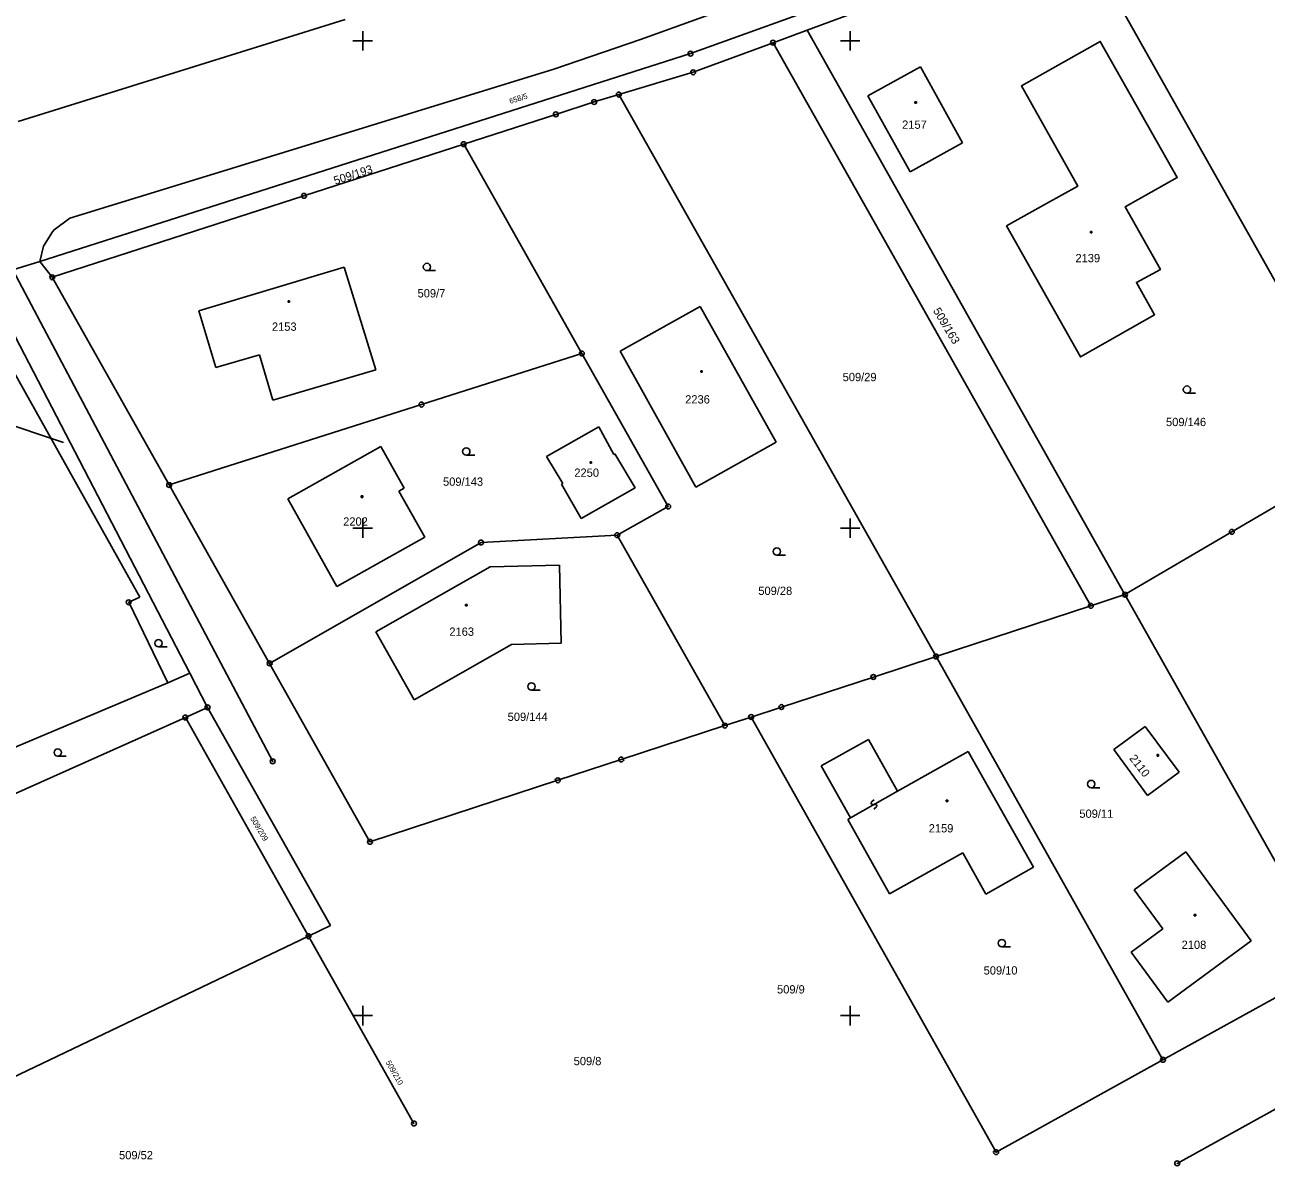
# Model space of a CAD drawing. Extents: x -493648 to -493033, y -1127718 to -1127026.
# Drawn here: x -493284.7 to -493157.3, y -1127716.4 to -1127598.4 of the extents above; entities that cross this region are included whole.
import ezdxf

# ---------------------------------------------------------------- set-up
doc = ezdxf.new("R2010")
doc.units = 0
doc.layers.add('katastrální mapa', color=7, linetype='Continuous')
doc.layers.add('síť', color=7, linetype='Continuous')

msp = doc.modelspace()

# ---------------------------------------------------------------- linework, layer by layer
at = {"layer": 'katastrální mapa'}
for p, q in [((-493178.63, -1127585.2), (-493150.81, -1127634.64)), ((-493191.17, -1127592.22), (-493216.38, -1127601.32)), ((-493204.41, -1127598.9), (-493192.39, -1127594.46)), ((-493285.34, -1127608.28), (-493251.78, -1127597.83)), ((-493207.91, -1127600.2), (-493204.41, -1127598.9)), ((-493171.81, -1127656.82), (-493204.41, -1127598.9)), ((-493216.1, -1127603.23), (-493207.91, -1127600.2)), ((-493175.31, -1127657.97), (-493207.91, -1127600.2)), ((-493283.12, -1127622.63), (-493216.38, -1127601.32)), ((-493192.8, -1127602.67), (-493198.17, -1127605.66)), ((-493188.47, -1127610.48), (-493192.8, -1127602.67)), ((-493223.72, -1127605.52), (-493216.1, -1127603.23)), ((-493226.26, -1127606.28), (-493223.72, -1127605.52)), ((-493223.72, -1127605.52), (-493191.19, -1127663.16)), ((-493198.17, -1127605.66), (-493193.84, -1127613.46)), ((-493230.19, -1127607.55), (-493226.26, -1127606.28)), ((-493193.36, -1127606.26), (-493193.21, -1127606.26)), ((-493193.36, -1127606.41), (-493193.36, -1127606.26)), ((-493193.21, -1127606.41), (-493193.36, -1127606.41)), ((-493193.21, -1127606.26), (-493193.21, -1127606.41)), ((-493239.64, -1127610.61), (-493230.19, -1127607.55)), ((-493256.02, -1127615.91), (-493239.64, -1127610.61)), ((-493227.52, -1127632.08), (-493239.64, -1127610.61)), ((-493193.84, -1127613.46), (-493188.47, -1127610.48)), ((-493281.84, -1127624.26), (-493256.02, -1127615.91)), ((-493175.36, -1127619.56), (-493175.21, -1127619.56)), ((-493175.36, -1127619.71), (-493175.36, -1127619.56)), ((-493175.21, -1127619.56), (-493175.21, -1127619.71)), ((-493175.21, -1127619.71), (-493175.36, -1127619.71)), ((-493285.88, -1127623.51), (-493283.12, -1127622.63)), ((-493285.88, -1127623.51), (-493259.23, -1127673.92)), ((-493281.84, -1127624.26), (-493283.12, -1127622.63)), ((-493251.9, -1127623.22), (-493266.82, -1127627.69)), ((-493248.64, -1127633.74), (-493251.9, -1127623.22)), ((-493288.74, -1127624.42), (-493267.72, -1127664.89)), ((-493281.84, -1127624.26), (-493269.85, -1127645.57)), ((-493243.41, -1127623.58), (-493242.53, -1127623.58)), ((-493290.17, -1127626.16), (-493272.87, -1127657.09)), ((-493257.64, -1127626.67), (-493257.49, -1127626.67)), ((-493257.64, -1127626.82), (-493257.64, -1127626.67)), ((-493257.49, -1127626.82), (-493257.64, -1127626.82)), ((-493257.49, -1127626.67), (-493257.49, -1127626.82)), ((-493215.38, -1127627.25), (-493223.6, -1127631.85)), ((-493207.59, -1127641.19), (-493215.38, -1127627.25)), ((-493266.82, -1127627.69), (-493265.05, -1127633.53)), ((-493265.05, -1127633.53), (-493260.6, -1127632.21)), ((-493260.6, -1127632.21), (-493259.2, -1127636.87)), ((-493243.97, -1127637.32), (-493227.52, -1127632.08)), ((-493218.66, -1127647.77), (-493227.52, -1127632.08)), ((-493223.6, -1127631.85), (-493215.82, -1127645.79)), ((-493259.2, -1127636.87), (-493248.64, -1127633.74)), ((-493215.33, -1127633.85), (-493215.18, -1127633.85)), ((-493215.33, -1127634), (-493215.33, -1127633.85)), ((-493215.18, -1127634), (-493215.33, -1127634)), ((-493215.18, -1127633.85), (-493215.18, -1127634)), ((-493165.45, -1127636.16), (-493164.57, -1127636.16)), ((-493269.85, -1127645.57), (-493243.97, -1127637.32)), ((-493280.68, -1127641.22), (-493287.85, -1127638.82)), ((-493225.79, -1127639.6), (-493231.14, -1127642.64)), ((-493225.79, -1127639.6), (-493224.24, -1127642.43)), ((-493215.82, -1127645.79), (-493207.59, -1127641.19)), ((-493257.69, -1127646.98), (-493248.13, -1127641.62)), ((-493248.13, -1127641.62), (-493245.73, -1127645.89)), ((-493239.37, -1127642.51), (-493238.49, -1127642.51)), ((-493224.24, -1127642.43), (-493224.13, -1127642.37)), ((-493222.06, -1127645.87), (-493224.13, -1127642.37)), ((-493160.85, -1127650.38), (-493146.64, -1127642.04)), ((-493229.48, -1127645.43), (-493231.14, -1127642.64)), ((-493226.67, -1127643.18), (-493226.52, -1127643.18)), ((-493226.67, -1127643.33), (-493226.67, -1127643.18)), ((-493226.52, -1127643.33), (-493226.67, -1127643.33)), ((-493226.52, -1127643.18), (-493226.52, -1127643.33)), ((-493269.85, -1127645.57), (-493259.55, -1127663.87)), ((-493245.73, -1127645.89), (-493246.3, -1127646.21)), ((-493246.3, -1127646.21), (-493243.64, -1127650.93)), ((-493229.61, -1127645.5), (-493229.48, -1127645.43)), ((-493229.61, -1127645.5), (-493227.58, -1127649.01)), ((-493227.58, -1127649.01), (-493222.06, -1127645.87)), ((-493252.65, -1127655.98), (-493257.69, -1127646.98)), ((-493250.14, -1127646.69), (-493249.99, -1127646.69)), ((-493250.14, -1127646.84), (-493250.14, -1127646.69)), ((-493249.99, -1127646.84), (-493250.14, -1127646.84)), ((-493249.99, -1127646.69), (-493249.99, -1127646.84)), ((-493223.89, -1127650.72), (-493218.66, -1127647.77)), ((-493259.55, -1127663.87), (-493237.86, -1127651.47)), ((-493243.64, -1127650.93), (-493252.65, -1127655.98)), ((-493223.89, -1127650.72), (-493237.86, -1127651.47)), ((-493223.89, -1127650.72), (-493212.86, -1127670.25)), ((-493160.85, -1127650.38), (-493171.81, -1127656.82)), ((-493207.52, -1127652.77), (-493206.64, -1127652.77)), ((-493248.66, -1127660.64), (-493236.94, -1127653.95)), ((-493236.94, -1127653.95), (-493229.8, -1127653.8)), ((-493229.8, -1127653.8), (-493229.63, -1127661.81)), ((-493272.87, -1127657.09), (-493274, -1127657.6)), ((-493274, -1127657.6), (-493269.99, -1127665.85)), ((-493239.44, -1127657.83), (-493239.29, -1127657.83)), ((-493239.44, -1127657.98), (-493239.44, -1127657.83)), ((-493239.29, -1127657.83), (-493239.29, -1127657.98)), ((-493175.31, -1127657.97), (-493171.81, -1127656.82)), ((-493171.81, -1127656.82), (-493150.41, -1127694.85)), ((-493239.29, -1127657.98), (-493239.44, -1127657.98)), ((-493191.19, -1127663.16), (-493175.31, -1127657.97)), ((-493244.72, -1127667.6), (-493248.66, -1127660.64)), ((-493270.94, -1127662.18), (-493270.06, -1127662.18)), ((-493234.74, -1127661.92), (-493244.72, -1127667.6)), ((-493229.63, -1127661.81), (-493234.74, -1127661.92)), ((-493259.55, -1127663.87), (-493249.25, -1127682.17)), ((-493197.62, -1127665.27), (-493191.19, -1127663.16)), ((-493191.19, -1127663.16), (-493167.91, -1127704.53)), ((-493269.99, -1127665.85), (-493267.72, -1127664.89)), ((-493267.72, -1127664.89), (-493265.91, -1127668.38)), ((-493207.05, -1127668.35), (-493197.62, -1127665.27)), ((-493269.99, -1127665.85), (-493287.47, -1127673.23)), ((-493232.69, -1127666.62), (-493231.81, -1127666.62)), ((-493268.19, -1127669.42), (-493265.91, -1127668.38)), ((-493265.91, -1127668.38), (-493253.3, -1127690.77)), ((-493210.16, -1127669.37), (-493207.05, -1127668.35)), ((-493322.12, -1127693.53), (-493268.19, -1127669.42)), ((-493255.56, -1127691.86), (-493268.19, -1127669.42)), ((-493212.86, -1127670.25), (-493223.48, -1127673.73)), ((-493210.16, -1127669.37), (-493212.86, -1127670.25)), ((-493210.16, -1127669.37), (-493185.03, -1127714.01)), ((-493172.97, -1127672.71), (-493169.75, -1127670.33)), ((-493169.75, -1127670.33), (-493166.25, -1127675.04)), ((-493202.96, -1127674.39), (-493198.11, -1127671.69)), ((-493198.11, -1127671.69), (-493195.13, -1127676.98)), ((-493195.13, -1127676.98), (-493187.9, -1127672.91)), ((-493187.9, -1127672.91), (-493181.21, -1127684.78)), ((-493169.49, -1127677.43), (-493172.97, -1127672.71)), ((-493281.28, -1127673.39), (-493280.4, -1127673.39)), ((-493229.99, -1127675.86), (-493223.48, -1127673.73)), ((-493199.97, -1127679.7), (-493202.96, -1127674.39)), ((-493168.51, -1127673.23), (-493168.36, -1127673.23)), ((-493168.51, -1127673.38), (-493168.51, -1127673.23)), ((-493168.36, -1127673.38), (-493168.51, -1127673.38)), ((-493168.36, -1127673.23), (-493168.36, -1127673.38)), ((-493166.25, -1127675.04), (-493169.49, -1127677.43)), ((-493249.25, -1127682.17), (-493229.99, -1127675.86)), ((-493199.97, -1127679.7), (-493195.13, -1127676.98)), ((-493175.27, -1127676.62), (-493174.39, -1127676.62)), ((-493197.81, -1127678.08), (-493197.85, -1127678.22)), ((-493197.85, -1127678.22), (-493197.8, -1127678.31)), ((-493197.53, -1127677.87), (-493197.81, -1127678.08)), ((-493190.14, -1127677.89), (-493189.99, -1127677.89)), ((-493190.14, -1127678.04), (-493190.14, -1127677.89)), ((-493189.99, -1127678.04), (-493190.14, -1127678.04)), ((-493189.99, -1127677.89), (-493189.99, -1127678.04)), ((-493197.8, -1127678.31), (-493197.66, -1127678.35)), ((-493197.66, -1127678.35), (-493197.44, -1127678.33)), ((-493197.29, -1127678.6), (-493197.57, -1127678.81)), ((-493197.44, -1127678.33), (-493197.3, -1127678.37)), ((-493197.3, -1127678.37), (-493197.25, -1127678.46)), ((-493197.25, -1127678.46), (-493197.29, -1127678.6)), ((-493200.25, -1127679.87), (-493199.97, -1127679.7)), ((-493200.25, -1127679.87), (-493195.95, -1127687.52)), ((-493195.95, -1127687.52), (-493188.44, -1127683.3)), ((-493188.44, -1127683.3), (-493186.07, -1127687.53)), ((-493165.58, -1127683.21), (-493170.87, -1127687.1)), ((-493158.86, -1127692.32), (-493165.58, -1127683.21)), ((-493186.07, -1127687.53), (-493181.21, -1127684.78)), ((-493170.87, -1127687.1), (-493167.92, -1127691.11)), ((-493164.7, -1127689.62), (-493164.55, -1127689.62)), ((-493164.7, -1127689.77), (-493164.7, -1127689.62)), ((-493164.55, -1127689.62), (-493164.55, -1127689.77)), ((-493255.56, -1127691.86), (-493253.3, -1127690.77)), ((-493164.55, -1127689.77), (-493164.7, -1127689.77)), ((-493306.9, -1127716.37), (-493255.56, -1127691.86)), ((-493244.74, -1127711.07), (-493255.56, -1127691.86)), ((-493167.92, -1127691.11), (-493171.16, -1127693.49)), ((-493184.44, -1127692.94), (-493183.56, -1127692.94)), ((-493171.16, -1127693.49), (-493167.4, -1127698.61)), ((-493167.4, -1127698.61), (-493158.86, -1127692.32)), ((-493167.91, -1127704.53), (-493150.41, -1127694.85)), ((-493185.03, -1127714.01), (-493167.91, -1127704.53)), ((-493166.45, -1127715.16), (-493150.2, -1127706.16))]:
    msp.add_line(p, q, dxfattribs=at)
for points in [[(-493097.31, -1127505.21), (-493098.12, -1127505.44), (-493098.98, -1127505.84), (-493107.13, -1127513.2), (-493127.98, -1127533.26), (-493136.84, -1127541.39), (-493149.38, -1127552.86), (-493159.12, -1127561.82), (-493168.03, -1127569.78), (-493174.01, -1127575.14), (-493177.93, -1127578.28), (-493182.72, -1127581.82), (-493186.93, -1127584.59), (-493191.56, -1127587.36), (-493199.02, -1127591.33), (-493200.84, -1127592.19), (-493208.3, -1127595.08), (-493221.5, -1127599.86), (-493230.41, -1127602.91), (-493259.01, -1127611.75), (-493280.04, -1127618.2), (-493281.66, -1127619.38), (-493281.8, -1127619.61)], [(-493183.97, -1127618.99), (-493176.38, -1127632.43), (-493168.78, -1127628.1), (-493170.63, -1127624.79), (-493168.17, -1127623.45), (-493171.78, -1127617.02), (-493166.44, -1127614.04), (-493174.35, -1127600.06), (-493182.44, -1127604.63), (-493176.66, -1127614.92), (-493179.85, -1127616.7), (-493183.97, -1127618.99)], [(-493281.8, -1127619.61), (-493282.74, -1127621.08), (-493283.12, -1127622.63)]]:
    msp.add_lwpolyline(points, dxfattribs=at)
for centre, radius in [((-493207.91, -1127600.2), 0.25), ((-493207.91, -1127600.2), 0.005), ((-493216.38, -1127601.32), 0.25), ((-493216.38, -1127601.32), 0.005), ((-493216.1, -1127603.23), 0.25), ((-493216.1, -1127603.23), 0.005), ((-493223.72, -1127605.52), 0.25), ((-493223.72, -1127605.52), 0.005), ((-493226.26, -1127606.28), 0.25), ((-493226.26, -1127606.28), 0.005), ((-493230.19, -1127607.55), 0.25), ((-493230.19, -1127607.55), 0.005), ((-493239.64, -1127610.61), 0.25), ((-493239.64, -1127610.61), 0.005), ((-493256.02, -1127615.91), 0.25), ((-493256.02, -1127615.91), 0.005), ((-493243.41, -1127623.205), 0.375), ((-493281.84, -1127624.26), 0.25), ((-493281.84, -1127624.26), 0.005), ((-493227.52, -1127632.08), 0.25), ((-493227.52, -1127632.08), 0.005), ((-493165.45, -1127635.785), 0.375), ((-493243.97, -1127637.32), 0.25), ((-493243.97, -1127637.32), 0.005), ((-493239.37, -1127642.135), 0.375), ((-493269.85, -1127645.57), 0.25), ((-493269.85, -1127645.57), 0.005), ((-493218.66, -1127647.77), 0.25), ((-493218.66, -1127647.77), 0.005), ((-493160.85, -1127650.38), 0.25), ((-493237.86, -1127651.47), 0.25), ((-493237.86, -1127651.47), 0.005), ((-493223.89, -1127650.72), 0.25), ((-493223.89, -1127650.72), 0.005), ((-493160.85, -1127650.38), 0.005), ((-493207.52, -1127652.395), 0.375), ((-493171.81, -1127656.82), 0.25), ((-493274, -1127657.6), 0.25), ((-493274, -1127657.6), 0.005), ((-493175.31, -1127657.97), 0.25), ((-493171.81, -1127656.82), 0.005), ((-493175.31, -1127657.97), 0.005), ((-493270.94, -1127661.805), 0.375), ((-493191.19, -1127663.16), 0.25), ((-493259.55, -1127663.87), 0.25), ((-493259.55, -1127663.87), 0.005), ((-493191.19, -1127663.16), 0.005), ((-493197.62, -1127665.27), 0.25), ((-493197.62, -1127665.27), 0.005), ((-493232.69, -1127666.245), 0.375), ((-493268.19, -1127669.42), 0.25), ((-493265.91, -1127668.38), 0.25), ((-493265.91, -1127668.38), 0.005), ((-493210.16, -1127669.37), 0.25), ((-493207.05, -1127668.35), 0.25), ((-493207.05, -1127668.35), 0.005), ((-493268.19, -1127669.42), 0.005), ((-493212.86, -1127670.25), 0.25), ((-493212.86, -1127670.25), 0.005), ((-493210.16, -1127669.37), 0.005), ((-493281.28, -1127673.015), 0.375), ((-493259.23, -1127673.92), 0.25), ((-493259.23, -1127673.92), 0.005), ((-493223.48, -1127673.73), 0.25), ((-493223.48, -1127673.73), 0.005), ((-493229.99, -1127675.86), 0.25), ((-493229.99, -1127675.86), 0.005), ((-493175.27, -1127676.245), 0.375), ((-493249.25, -1127682.17), 0.25), ((-493249.25, -1127682.17), 0.005), ((-493255.56, -1127691.86), 0.25), ((-493255.56, -1127691.86), 0.005), ((-493184.44, -1127692.565), 0.375), ((-493167.91, -1127704.53), 0.25), ((-493167.91, -1127704.53), 0.005), ((-493244.74, -1127711.07), 0.25), ((-493244.74, -1127711.07), 0.005), ((-493185.03, -1127714.01), 0.25), ((-493185.03, -1127714.01), 0.005), ((-493166.45, -1127715.16), 0.25), ((-493166.45, -1127715.16), 0.005)]:
    msp.add_circle(centre, radius, dxfattribs=at)
at = {"layer": 'síť'}
for p, q in [((-493250, -1127599), (-493250, -1127601)), ((-493200, -1127599), (-493200, -1127601)), ((-493251, -1127600), (-493249, -1127600)), ((-493201, -1127600), (-493199, -1127600)), ((-493251, -1127650), (-493249, -1127650)), ((-493250, -1127649), (-493250, -1127651)), ((-493201, -1127650), (-493199, -1127650)), ((-493200, -1127649), (-493200, -1127651)), ((-493250, -1127699), (-493250, -1127701)), ((-493200, -1127699), (-493200, -1127701)), ((-493251, -1127700), (-493249, -1127700)), ((-493201, -1127700), (-493199, -1127700))]:
    msp.add_line(p, q, dxfattribs=at)

# ---------------------------------------------------------------- texts
at = {"layer": 'katastrální mapa'}
for s, height, rotation, p in [('658/5', 0.569994, 17.4114889, (-493234.86, -1127606.48)), ('509/193', 0.849996, 17.9999972, (-493252.81, -1127614.78)), ('509/163', 0.849996, 300.9482083, (-493191.53, -1127627.69)), ('2110', 0.849996, 307.8, (-493171.41, -1127673.63)), ('509/209', 0.569994, 300.6560694, (-493261.55, -1127679.79)), ('509/210', 0.569994, 299.7273583, (-493247.66, -1127704.8))]:
    msp.add_text(s, height=height, rotation=rotation, dxfattribs=at).set_placement(p)
for s, height, p in [('2157', 0.849996, (-493194.67, -1127609.03)), ('2139', 0.849996, (-493176.89, -1127622.72)), ('509/7', 0.849996, (-493244.37, -1127626.33)), ('2153', 0.849996, (-493259.31, -1127629.75)), ('509/29', 0.849996, (-493200.77, -1127634.92)), ('2236', 0.849996, (-493216.92, -1127637.21)), ('509/146', 0.849996, (-493167.6, -1127639.53)), ('568/3', 0.049998, (-493280.78, -1127641.22)), ('2250', 0.849996, (-493228.29, -1127644.73)), ('509/143', 0.849996, (-493241.76, -1127645.65)), ('2202', 0.849996, (-493252, -1127649.74)), ('509/28', 0.849996, (-493209.42, -1127656.85)), ('2163', 0.849996, (-493241.11, -1127661.04)), ('509/144', 0.849996, (-493235.13, -1127669.77)), ('509/11', 0.849996, (-493176.49, -1127679.71)), ('2159', 0.849996, (-493191.94, -1127681.21)), ('2108', 0.849996, (-493166, -1127693.16)), ('509/10', 0.849996, (-493186.31, -1127695.79)), ('509/9', 0.849996, (-493207.5, -1127697.73)), ('509/8', 0.849996, (-493228.36, -1127705.09)), ('509/52', 0.849996, (-493274.99, -1127714.74))]:
    msp.add_text(s, height=height, dxfattribs=at).set_placement(p)

doc.saveas('drawing.dxf')
